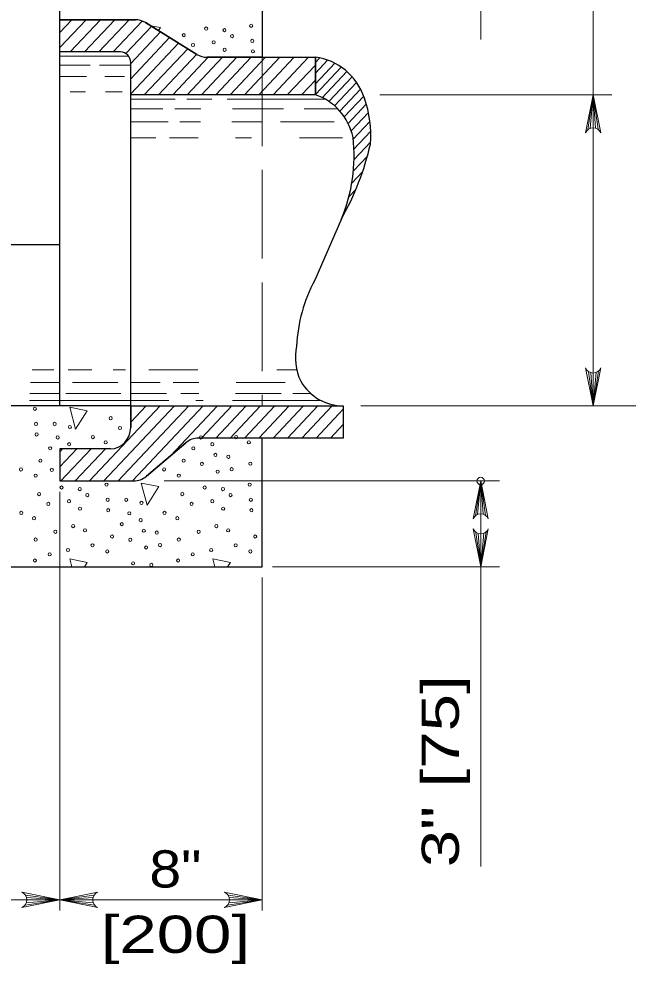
# Model space of a CAD drawing. Extents: x 1352.5 to 1386.5, y 735.9 to 779.9.
# Drawn here: x 1379.06 to 1381.616, y 768.997 to 772.96 of the extents above; entities that cross this region are included whole.
import ezdxf
from ezdxf.enums import TextEntityAlignment as Align

# ---------------------------------------------------------------- set-up
doc = ezdxf.new("R2010")
doc.units = 0
doc.header["$LTSCALE"] = 0.062
doc.header["$PDMODE"] = 32
doc.header["$PDSIZE"] = 0.031
doc.linetypes.add('LONG_DASHED', pattern=[7.5, 6, -1.5])
doc.layers.add('1', color=7, linetype='Continuous', lineweight=13)

msp = doc.modelspace()

# ---------------------------------------------------------------- linework, layer by layer
at = {"layer": '1'}
for p, q in [((1380.99775, 772.87267), (1380.99775, 775.72767)), ((1381.46975, 771.337), (1381.46975, 774.74983)), ((1379.23192, 772.83908), (1379.34242, 772.95608)), ((1379.23192, 772.90267), (1379.28242, 772.95608)), ((1379.275, 772.82117), (1379.4025, 772.95608)), ((1379.33517, 772.82117), (1379.46258, 772.95608)), ((1379.39517, 772.82117), (1379.52267, 772.95608)), ((1379.45525, 772.82117), (1379.57767, 772.95075)), ((1379.50908, 772.8145), (1379.61667, 772.92842)), ((1379.52925, 772.77233), (1379.65467, 772.905)), ((1379.52925, 772.70867), (1379.6925, 772.8815)), ((1379.52925, 772.64508), (1379.7305, 772.85817)), ((1379.23192, 772.80317), (1379.52075, 772.80317)), ((1379.58575, 772.64125), (1379.76842, 772.83467)), ((1379.64583, 772.64125), (1379.80642, 772.81125)), ((1379.70592, 772.64125), (1379.85458, 772.79867)), ((1379.76592, 772.64125), (1379.91467, 772.79867)), ((1379.82608, 772.64125), (1379.97475, 772.79867)), ((1379.88608, 772.64125), (1380.03475, 772.79867)), ((1379.94625, 772.64125), (1380.09492, 772.79867)), ((1380.00625, 772.64125), (1380.155, 772.79867)), ((1380.06633, 772.64125), (1380.215, 772.79867)), ((1380.12642, 772.64125), (1380.27517, 772.79867)), ((1379.23192, 772.76625), (1379.35942, 772.76625)), ((1379.39783, 772.76625), (1379.52925, 772.76625)), ((1380.1865, 772.64125), (1380.30442, 772.766)), ((1380.30433, 772.77683), (1380.32225, 772.79583)), ((1380.30433, 772.73225), (1380.35575, 772.78675)), ((1380.30433, 772.68775), (1380.38558, 772.77383)), ((1379.23192, 772.71867), (1379.34333, 772.71867)), ((1379.42033, 772.71867), (1379.50375, 772.71867)), ((1380.30433, 772.64325), (1380.41242, 772.75767)), ((1380.33325, 772.62933), (1380.43658, 772.73875)), ((1380.24658, 772.64125), (1380.30442, 772.70242)), ((1380.3605, 772.61367), (1380.45808, 772.71708)), ((1380.38483, 772.59492), (1380.47708, 772.69258)), ((1379.276, 772.65417), (1379.34017, 772.65417)), ((1379.42358, 772.65417), (1379.49408, 772.65417)), ((1380.40633, 772.57317), (1380.49342, 772.66533)), ((1380.57508, 772.64125), (1381.54842, 772.64125)), ((1381.4475, 772.49533), (1381.46975, 772.64125)), ((1381.45683, 772.50092), (1381.46975, 772.64125)), ((1381.46975, 772.50342), (1381.46975, 772.64125)), ((1381.48, 772.50192), (1381.46975, 772.64125)), ((1381.49, 772.49708), (1381.46975, 772.64125)), ((1379.52925, 772.62333), (1379.716, 772.62333)), ((1379.76442, 772.62333), (1379.86925, 772.62333)), ((1379.93342, 772.62333), (1380.345, 772.62333)), ((1380.42517, 772.54867), (1380.50683, 772.63517)), ((1380.44133, 772.52117), (1380.51775, 772.60208)), ((1379.52925, 772.58292), (1379.66408, 772.58292)), ((1379.71475, 772.58292), (1379.82425, 772.58292)), ((1379.956, 772.58292), (1380.17075, 772.58292)), ((1380.25733, 772.58292), (1380.39742, 772.58292)), ((1380.45425, 772.49033), (1380.52667, 772.56692)), ((1379.52925, 772.52758), (1379.687, 772.52758)), ((1379.73483, 772.52758), (1379.822, 772.52758)), ((1379.95383, 772.52758), (1380.07767, 772.52758)), ((1380.15792, 772.52758), (1380.38233, 772.52758)), ((1380.46292, 772.455), (1380.53292, 772.52908)), ((1380.46592, 772.41367), (1380.53608, 772.488)), ((1379.52925, 772.46067), (1379.63517, 772.46067)), ((1379.69242, 772.46067), (1379.81308, 772.46067)), ((1379.96942, 772.46067), (1380.036, 772.46067)), ((1380.23808, 772.46067), (1380.41758, 772.46067)), ((1380.46642, 772.36967), (1380.53567, 772.44292)), ((1380.46375, 772.32225), (1380.52233, 772.38433)), ((1380.45692, 772.27058), (1380.50208, 772.31833)), ((1380.44467, 772.213), (1380.47383, 772.24392)), ((1380.42342, 772.14608), (1380.43208, 772.15517)), ((1379.11608, 771.48875), (1379.20708, 771.48875)), ((1379.26642, 771.48875), (1379.36575, 771.48875)), ((1379.45567, 771.48875), (1379.50692, 771.48875)), ((1379.60525, 771.48875), (1379.81083, 771.48875)), ((1380.14183, 771.48875), (1380.22608, 771.48875)), ((1381.44958, 771.48125), (1381.46975, 771.337)), ((1381.45958, 771.47633), (1381.46975, 771.337)), ((1381.49208, 771.48292), (1381.46975, 771.337)), ((1381.48275, 771.47742), (1381.46975, 771.337)), ((1381.46975, 771.47492), (1381.46975, 771.337)), ((1379.10933, 771.4345), (1379.23192, 771.4345)), ((1379.28567, 771.4345), (1379.47483, 771.4345)), ((1379.52925, 771.4345), (1379.65317, 771.4345)), ((1379.70808, 771.4345), (1379.81525, 771.4345)), ((1379.97167, 771.4345), (1380.17708, 771.4345)), ((1379.10592, 771.38875), (1379.23192, 771.38875)), ((1379.25675, 771.38875), (1379.48767, 771.38875)), ((1379.52925, 771.38875), (1379.68025, 771.38875)), ((1379.73933, 771.38875), (1379.81525, 771.38875)), ((1379.96942, 771.38875), (1380.16108, 771.38875)), ((1380.20917, 771.38875), (1380.28558, 771.38875)), ((1379.35625, 771.02225), (1379.65358, 771.33708)), ((1379.41625, 771.02225), (1379.71367, 771.33708)), ((1379.47642, 771.02225), (1379.77375, 771.33708)), ((1379.52925, 771.26908), (1379.59358, 771.33708)), ((1379.52925, 771.33258), (1379.53342, 771.33708)), ((1379.53642, 771.02225), (1379.83383, 771.33708)), ((1379.69575, 771.12725), (1379.89392, 771.33708)), ((1379.80208, 771.3595), (1379.83317, 771.3595)), ((1379.8265, 771.20208), (1379.954, 771.33708)), ((1379.88658, 771.20208), (1380.014, 771.33708)), ((1379.94667, 771.20208), (1380.07417, 771.33708)), ((1379.956, 771.3595), (1380.328, 771.3595)), ((1380.00675, 771.20208), (1380.13417, 771.33708)), ((1380.06683, 771.20208), (1380.19433, 771.33708)), ((1380.12692, 771.20208), (1380.25433, 771.33708)), ((1380.187, 771.20208), (1380.31442, 771.33708)), ((1380.247, 771.20208), (1380.3745, 771.33708)), ((1380.49558, 771.337), (1382.02108, 771.337)), ((1379.34717, 771.31683), (1379.2735, 771.33117)), ((1380.30717, 771.20208), (1380.42133, 771.323)), ((1380.36717, 771.20208), (1380.42133, 771.25942)), ((1379.23192, 771.08133), (1379.3035, 771.15717)), ((1379.23192, 771.145), (1379.24342, 771.15717)), ((1379.23608, 771.02225), (1379.3635, 771.15717)), ((1379.29608, 771.02225), (1379.42367, 771.15717)), ((1379.66942, 771.02225), (1381.07642, 771.02225)), ((1380.9755, 770.87633), (1380.99775, 771.02225)), ((1380.98483, 770.88183), (1380.99775, 771.02225)), ((1380.99775, 770.88433), (1380.99775, 771.02225)), ((1381.008, 770.88292), (1380.99775, 771.02225)), ((1381.018, 770.878), (1380.99775, 771.02225)), ((1380.99775, 771.02225), (1380.99775, 769.406)), ((1379.23192, 770.97725), (1379.23192, 769.22067)), ((1380.97758, 770.80667), (1380.99775, 770.66242)), ((1380.98758, 770.80175), (1380.99775, 770.66242)), ((1381.02008, 770.80833), (1380.99775, 770.66242)), ((1381.01075, 770.80283), (1380.99775, 770.66242)), ((1380.99775, 770.80025), (1380.99775, 770.66242)), ((1379.2735, 770.69517), (1379.28208, 770.6625)), ((1379.87417, 770.69517), (1379.88283, 770.66242)), ((1380.124, 770.66242), (1381.07642, 770.66242)), ((1380.0815, 770.61742), (1380.0815, 769.22067)), ((1379.08767, 769.28583), (1379.23192, 769.26567)), ((1379.09258, 769.27583), (1379.23192, 769.26567)), ((1379.37617, 769.28583), (1379.23192, 769.26567)), ((1379.37125, 769.27583), (1379.23192, 769.26567)), ((1379.93725, 769.28583), (1380.0815, 769.26567)), ((1379.94217, 769.27583), (1380.0815, 769.26567)), ((1377.39175, 769.26567), (1379.23192, 769.26567)), ((1379.086, 769.24333), (1379.23192, 769.26567)), ((1379.0915, 769.25275), (1379.23192, 769.26567)), ((1379.09408, 769.26567), (1379.23192, 769.26567)), ((1379.23192, 769.26567), (1379.82017, 769.26567)), ((1379.36975, 769.26567), (1379.23192, 769.26567)), ((1379.37233, 769.25275), (1379.23192, 769.26567)), ((1379.37783, 769.24333), (1379.23192, 769.26567)), ((1379.82017, 769.26567), (1380.0815, 769.26567)), ((1379.93558, 769.24333), (1380.0815, 769.26567)), ((1379.94108, 769.25275), (1380.0815, 769.26567)), ((1379.94367, 769.26567), (1380.0815, 769.26567))]:
    msp.add_line(p, q, dxfattribs=at)
at = {"layer": '1', "lineweight": 25}
for p, q in [((1379.54883, 772.95608), (1379.23192, 772.95608)), ((1379.59158, 772.94392), (1379.80683, 772.811)), ((1379.80683, 772.811), (1379.59158, 772.94392)), ((1379.23192, 771.33708), (1379.23192, 772.82117)), ((1379.48675, 772.82117), (1379.23192, 772.82117)), ((1380.30433, 772.64125), (1380.30433, 772.79867)), ((1379.52925, 771.33708), (1379.52925, 772.64125)), ((1380.41367, 772.1215), (1380.3015, 771.86417)), ((1379.23192, 772.01167), (1376.42825, 772.01167)), ((1379.52925, 771.33708), (1379.52925, 771.24708)), ((1379.595, 771.04192), (1379.76083, 771.18242)), ((1379.76083, 771.18242), (1379.595, 771.04192)), ((1379.23192, 771.15717), (1379.23192, 771.02225)), ((1379.44433, 771.15717), (1379.23192, 771.15717)), ((1379.23192, 771.02225), (1379.54192, 771.02225))]:
    msp.add_line(p, q, dxfattribs=at)
at = {"layer": '1', "linetype": 'LONG_DASHED'}
msp.add_line((1380.0815, 772.79867), (1380.0815, 771.33708), dxfattribs=at)
at = {"layer": '1', "lineweight": 25}
for points in [[(1379.23192, 772.95608), (1379.23192, 776.14925), (1380.0815, 776.14925), (1380.0815, 772.79867), (1379.84958, 772.79867)], [(1379.23192, 772.82117), (1379.23192, 772.95608), (1379.54883, 772.95608)], [(1379.84958, 772.79867), (1380.30433, 772.79867), (1380.30433, 772.64125), (1379.52925, 772.64125), (1379.52925, 772.77625)], [(1379.52925, 771.24708), (1379.52925, 771.33708), (1378.65958, 771.33708)], [(1379.52925, 771.33708), (1380.0815, 771.33708), (1380.42133, 771.33708), (1380.42133, 771.20208), (1380.0815, 771.20208)], [(1375.57867, 770.66242), (1380.0815, 770.66242), (1380.0815, 771.20208), (1379.81392, 771.20208)]]:
    msp.add_lwpolyline(points, dxfattribs=at)
at = {"layer": '1'}
for points in [[(1379.64575, 772.91042), (1379.65375, 772.92292), (1379.6125, 772.931)], [(1381.43792, 772.482), (1381.46975, 772.64125), (1381.50167, 772.482)], [(1381.50167, 771.49633), (1381.46975, 771.337), (1381.43792, 771.49633)], [(1379.10475, 771.3595), (1379.23192, 771.3595), (1379.68925, 771.3595)], [(1379.2735, 771.33117), (1379.29775, 771.23908), (1379.34717, 771.31683)], [(1380.96592, 770.86292), (1380.99775, 771.02225), (1381.02967, 770.86292)], [(1381.02967, 770.82175), (1380.99775, 770.66242), (1380.96592, 770.82175)], [(1379.3355, 770.6625), (1379.34717, 770.68075), (1379.2735, 770.69517)], [(1379.93617, 770.66242), (1379.948, 770.68075), (1379.87417, 770.69517)], [(1379.07258, 769.23383), (1379.23192, 769.26567), (1379.07258, 769.2975)], [(1379.39117, 769.23383), (1379.23192, 769.26567), (1379.39117, 769.2975)], [(1379.92217, 769.23383), (1380.0815, 769.26567), (1379.92217, 769.2975)]]:
    msp.add_lwpolyline(points, dxfattribs=at)
msp.add_lwpolyline([(1379.57383, 771.01325), (1379.59808, 770.921), (1379.64758, 770.99883)], close=True, dxfattribs=at)
for centre, start, end in [((1381.46982, 772.46912), 22.08782, 157.91395), ((1381.46975, 771.5092), 202.08782, 337.91395), ((1380.99783, 770.85005), 22.08782, 157.91395), ((1380.99776, 770.83459), 202.08782, 337.91395), ((1379.05974, 769.2657), 292.08605, 67.91218), ((1379.40407, 769.2657), 112.08782, 247.91395), ((1379.90934, 769.2657), 292.08605, 67.91218)]:
    msp.add_arc(centre, 0.03438, start, end, dxfattribs=at)
at = {"layer": '1', "lineweight": 25}
for centre, major_axis, start_param, end_param in [((1379.54878, 772.86616), (0, 0.08995), 5.7551109, 6.2831853), ((1379.54878, 772.86616), (0, 0.08995), 5.7551109, 6.2831853), ((1379.48679, 772.77621), (0, 0.04497), 4.712389, 6.2831853), ((1379.8496, 772.88864), (0, -0.08995), 5.755036, 6.2831853), ((1379.8496, 772.88864), (0, -0.08995), 5.755036, 6.2831853), ((1380.27775, 772.53933), (0, 0.26089), 5.0559079, 6.1751806), ((1380.23501, 772.40506), (0, 0.24736), 4.9480586, 5.9820436), ((1380.11483, 772.47068), (0, 0.44647), 4.6325583, 5.0705493), ((1379.853, 772.38529), (0, 0.64961), 4.2941677, 4.8320144), ((1379.50941, 772.6973), (0, -1.11722), 1.0292935, 1.3338755), ((1380.81782, 771.55393), (0, 0.62853), 1.0546473, 1.5164599), ((1380.43032, 771.54088), (0, 0.22241), 1.357022, 2.0384097), ((1380.4199, 771.55852), (0, -0.22149), 5.2736831, 6.2901088), ((1379.44431, 771.24709), (0, -0.08995), 6.2831853, 7.8539816), ((1379.44431, 771.24709), (0, -0.08995), 6.2831853, 7.8539816), ((1379.81395, 771.11217), (0, 0.08995), 6.2831853, 6.9579719), ((1379.81395, 771.11217), (0, 0.08995), 6.2831853, 6.9579719), ((1379.54195, 771.11217), (0, -0.08995), 6.2831853, 6.9579263)]:
    msp.add_ellipse(centre, major_axis=major_axis, ratio=0.944544, start_param=start_param, end_param=end_param, dxfattribs=at)
at = {"layer": '1'}
for centre in [(1379.84605, 772.91894), (1379.92259, 772.91232), (1380.03479, 772.93092), (1379.75198, 772.89143), (1379.95448, 772.88714), (1379.79093, 772.8502), (1379.87769, 772.86138), (1380.03964, 772.86737), (1379.92339, 772.83016), (1380.04204, 772.82359), (1379.12751, 771.32485), (1379.44546, 771.28537), (1379.13237, 771.2613), (1379.21027, 771.2613), (1379.2743, 771.24842), (1379.13477, 771.21752), (1379.37082, 771.20634), (1379.48441, 771.24413), (1379.97158, 771.20634), (1379.22323, 771.20464), (1379.27104, 771.17629), (1379.42434, 771.18403), (1379.82399, 771.20464), (1379.8718, 771.17629), (1380.02509, 771.18403), (1379.19154, 771.15912), (1379.7923, 771.15912), (1379.88482, 771.13166), (1379.15074, 771.10733), (1379.7515, 771.10733), (1379.828, 771.09387), (1379.93914, 771.12387), (1380.0316, 771.09466), (1379.06879, 771.07039), (1379.19843, 771.06839), (1379.66955, 771.07039), (1379.89448, 771.06122), (1379.9529, 771.07156), (1379.13047, 771.04463), (1379.73122, 771.04463), (1379.23915, 770.99486), (1379.3157, 770.98824), (1379.42789, 771.00684), (1379.83991, 770.99486), (1379.91646, 770.98824), (1380.02865, 771.00684), (1379.14508, 770.96735), (1379.27079, 770.9373), (1379.34759, 770.96306), (1379.43275, 770.94329), (1379.51064, 770.94329), (1379.57468, 770.93041), (1379.74584, 770.96735), (1379.87155, 770.9373), (1379.94835, 770.96306), (1380.0335, 770.94329), (1379.18403, 770.92612), (1379.3165, 770.90608), (1379.43515, 770.89951), (1379.78479, 770.92612), (1379.91726, 770.90608), (1380.03591, 770.89951), (1379.07044, 770.88833), (1379.12396, 770.86601), (1379.52361, 770.88663), (1379.57142, 770.85827), (1379.6712, 770.88833), (1379.72471, 770.86601), (1379.28811, 770.8331), (1379.33758, 770.81508), (1379.49192, 770.8411), (1379.58444, 770.81365), (1379.88887, 770.8331), (1379.93833, 770.81508), (1379.13047, 770.77665), (1379.21347, 770.80909), (1379.45112, 770.78932), (1379.52762, 770.77585), (1379.63876, 770.80585), (1379.73122, 770.77665), (1379.81423, 770.80909), (1380.05188, 770.78932), (1379.26619, 770.7326), (1379.36917, 770.75237), (1379.5941, 770.7432), (1379.65252, 770.75354), (1379.86694, 770.7326), (1379.96992, 770.75237), (1379.18909, 770.71458), (1379.43084, 770.72662), (1379.78985, 770.71458), (1380.0316, 770.72662), (1379.12751, 770.68882), (1379.53953, 770.67685), (1379.61608, 770.67022), (1379.72827, 770.68882)]:
    msp.add_ellipse(centre, major_axis=(0, 0.0068), ratio=0.944544, dxfattribs=at)
msp.add_ellipse((1379.54195, 771.11217), major_axis=(0, -0.08995), ratio=0.944544, start_param=6.2831853, end_param=6.9579263, dxfattribs=at)
msp.add_point((1380.99775, 771.02225), dxfattribs=at)

# ---------------------------------------------------------------- texts
at = {"layer": '1', "width": 1.35}
msp.add_text('3" [75]', height=0.156, rotation=90, dxfattribs=at).set_placement((1380.90617, 769.40275))
at = {"layer": '1'}
for s, width, p in [('8"', 1.15, (1379.71692, 769.31758)), ('[200]', 1.35, (1379.71692, 769.04358))]:
    msp.add_text(s, height=0.156, dxfattribs=dict(at, width=width)).set_placement(p, align=Align.CENTER)

doc.saveas('drawing.dxf')
